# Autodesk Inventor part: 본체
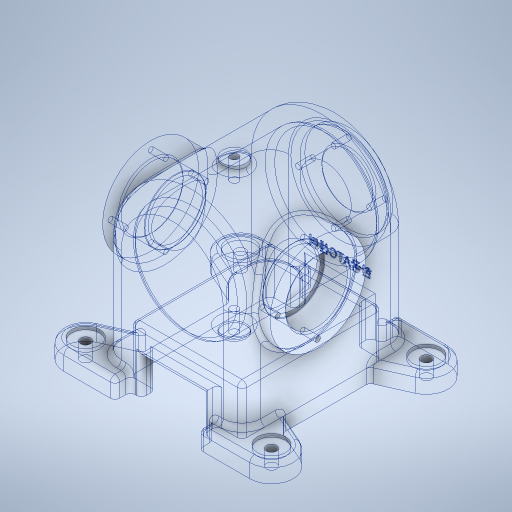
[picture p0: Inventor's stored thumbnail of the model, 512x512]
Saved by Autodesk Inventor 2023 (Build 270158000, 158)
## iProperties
Created: 2024-09
Part Number: 본체
Material: 알루미늄 6061
Document SubType Name: Modeling
Designer: home
Density: 2.7 g/cm^3
Appearance: 알루미늄 - 평지
Mass: 1473.92 g
Surface Area: 1119.68 cm^2
Volume: 545.898 cm^3
Author: home
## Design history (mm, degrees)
sketch "스케치1" dims "d2" = 90
  geometry: L1 (-45, 76)-(45, 76); L2 (45, 76)-(45, 0); L3 (45, 0)-(-45, 0); L4 (-45, 0)-(-45, 76); 6 further points
  constraints: 8 end point, 2 midpoint, 2 parallel, 1 coincident, 1 horizontal, 1 perpendicular, 3 other
  dimensions: "d0" = 90 distance of L2.end L3.end; "d7" = 121 distance from line of L3 point (0, 121); "d8" = 76 distance of L3.end L1.start
extrude "돌출1" new body sketch "스케치1" stored distance "d3" = 108; taper "d4" = 0 deg
sketch "스케치2"
  geometry: L1 (-45, 0)-(45, 0) reference; C1 r 28.5 at (0, 76); 1 further point
  constraints: 1 centre point
  dimensions: "d5" = 57 diameter of C1; "d6" = 76 distance from line of L1 C1.centre
extrude "돌출2" join sketch "스케치2" distance "d9" = 6; taper "d10" = 0 deg
node "작업 평면1"
sketch "스케치4"
  geometry: C1 r 16.5 at (0, 0); 1 further point
  constraints: 1 centre point, 1 vertical alignment
  dimensions: "d16" = 33 diameter of C1
extrude "돌출3" cut sketch "스케치4" distance "d17" = 15; taper "d18" = 0 deg
sketch "스케치6"
  geometry: L1 (27, 64)-(60, 64); L2 (65.693, 37.21)-(45, 28); L3 (45, 54)-(-45, 54) reference; L4 (45, 54)-(45, -54) reference; L5 (27, 64)-(27, 54); L6 (0, 54)-(0, 0); L7 (45, -54)-(45, 54) reference; A1 r 14 centre (60, 50) between (60, 64) and (65.693, 37.21); 3 further points
  constraints: 8 end point, 2 point on circle, 2 tangent, 2 vertical, 1 centre point, 1 coincident, 1 horizontal alignment, 1 midpoint, 1 vertical alignment
  dimensions: "d23" = 36 distance from line of L1 point (45, 28); "d25" = 18 distance from line of L4 L1.start; "d26" = 60 distance from line of L6 A1.centre; "d27" = 50 vertical distance of A1.centre L6.end; "d28" = 14 distance from line of L1 A1.centre
extrude "돌출5" join sketch "스케치6" distance "d29" = 12; taper "d30" = 0 deg
sketch "스케치7"
  geometry: L1 (-60, -64)-(-27, -64) reference; L2 (0, 66.899)-(0, -57.494); 2 further points
  constraints: 2 end point, 1 vertical
  dimensions: "d32" = 14 distance from line of L1 point (-60, -50); "d33" = 60 horizontal distance of point (-60, -50) L2.end
hole "구멍1" sketch "스케치7" at (-60, -50) diameter "d34" = 6.6; stored, may be unused: countersink angle "d38" = 90 deg, drill point angle "d40" = 0 deg; dims "d35" = 6, "d36" = 18, "d37" = 2, "d39" = 12
sketch "스케치8"
  geometry: L1 (-20, 23)-(20, 23); L2 (20, 23)-(20, 0); L3 (20, 0)-(-20, 0); L4 (-20, 0)-(-20, 23); L5 (-27, 0)-(27, 0) reference; 2 further points
  constraints: 8 end point, 2 midpoint, 2 parallel, 1 horizontal, 1 perpendicular
  dimensions: "d41" = 40 distance of L2.end L3.end; "d42" = 23 distance of L3.end L1.start
extrude "돌출6" cut sketch "스케치8" extent not by distance; stored distance "d43" = 0; taper "d44" = 0 deg
sketch "스케치9"
  geometry: L1 (-63, -19)-(9, -19); L2 (9, -19)-(9, -109); L3 (9, -109)-(-63, -109); L4 (-63, -109)-(-63, -19); L5 (-63, -19)-(9, -109); L6 (9, -19)-(-63, -109); L7 (18, -92)-(18, -36) reference; L8 (-55.5, -124)-(1.5, -124) reference; L9 (0, -118)-(-7, -118) reference; 1 further point
  constraints: 12 end point, 2 midpoint, 2 parallel, 1 horizontal, 1 perpendicular
  dimensions: "d45" = 9 distance between parallel lines of L7 L2; "d47" = 9 distance between parallel lines of L9 L3
extrude "돌출7" cut sketch "스케치9" distance "d48" = 31; taper "d49" = 0 deg
node "작업 평면2"
sketch "스케치10"
  geometry: L1 (-28.5, -60)-(28.5, -60) reference; C1 r 7.5 at (0, 14); 1 further point
  constraints: 1 centre point, 1 vertical alignment
  dimensions: "d51" = 74 distance from line of L1 C1.centre; "d52" = 15 diameter of C1
extrude "돌출8" join sketch "스케치10" distance "d53" = 7; taper "d54" = 0 deg
node "작업 평면3"
sketch "스케치11"
  geometry: 2 further points
hole "구멍2" sketch "스케치11" at (0, 0) diameter "d56" = 5.1881; stored, may be unused: countersink angle "d60" = 90 deg, drill point angle "d62" = 0 deg; dims "d57" = 12, "d58" = 18, "d59" = 2, "d61" = 8
fillet "모깎기2" dims "d63" = 3
sketch "스케치12" dims "d64" = 46
  geometry: 3 further points
  constraints: 1 vertical alignment, 2 other
hole "구멍3" sketch "스케치12" at (0, 23) diameter "d65" = 3.242; stored, may be unused: countersink angle "d69" = 90 deg, drill point angle "d71" = 0 deg; dims "d66" = 8, "d67" = 4, "d68" = 2, "d70" = 10
fillet "모깎기3" dims "d75" = 12
fillet "모깎기4" dims "d76" = 3
fillet "모깎기5" dims "d77" = 3
fillet "모깎기6" dims "d78" = 3
fillet "모깎기7" dims "d79" = 3
node "작업 평면4"
sketch "스케치13"
  geometry: L1 (54, -31)-(-54, -31); L2 (-54, -31)-(-54, 31); L3 (-54, 31)-(54, 31); L4 (54, 31)-(54, -31); L5 (54, -31)-(-54, 31); L6 (-54, -31)-(54, 31); L7 (-54, 0)-(54, 0); L8 (-60, -76)-(-74, -76) reference; 4 further points
  constraints: 14 end point, 5 midpoint, 2 parallel, 1 horizontal, 1 perpendicular, 1 vertical alignment
  dimensions: "d81" = 62 diameter of L3 L7; "d82" = 76 distance between parallel lines of L8 L7; "d83" = 108 distance of L2.end L3.end
revolve "회전2" sketch "스케치13" stored, may be unused: angle "d84" = 90 deg
sketch "스케치14"
  geometry: C1 r 20 at (0, 0); 1 further point
  constraints: 1 centre point
  dimensions: "d85" = 40 diameter of C1
extrude "돌출9" cut sketch "스케치14" distance "d86" = 16; taper "d87" = 0 deg
sketch "스케치15"
  geometry: C1 r 17.5 at (0, 0); 1 further point
  constraints: 1 centre point
  dimensions: "d88" = 35 diameter of C1
extrude "돌출10" cut sketch "스케치15" extent not by distance; stored distance "d89" = 0; taper "d90" = 0 deg
sketch "스케치16"
  geometry: C1 r 20 at (0, 0); 1 further point
  constraints: 1 centre point
  dimensions: "d91" = 40 diameter of C1
extrude "돌출11" cut sketch "스케치16" distance "d92" = 16; taper "d93" = 0 deg
fillet "모깎기8" dims "d94" = 0.3
sketch "스케치17" dims "d95" = 52
  geometry: 3 further points
  constraints: 1 vertical alignment, 2 other
hole "구멍4" sketch "스케치17" at (0, 26) diameter "d96" = 3.242; stored, may be unused: countersink angle "d100" = 90 deg, drill point angle "d102" = 0 deg; dims "d97" = 8, "d98" = 4, "d99" = 2, "d101" = 10
fillet "모깎기9" dims "d106" = 3
chamfer "모따기1" distance "d107" = 1; stored, may be unused: second distance "d108" = 2, angle "d109" = 45 deg
chamfer "모따기2" distance "d110" = 1; stored, may be unused: second distance "d111" = 2, angle "d112" = 45 deg
chamfer "모따기3" distance "d113" = 1; stored, may be unused: second distance "d114" = 2, angle "d115" = 45 deg
sketch "스케치18"
  geometry: L1 (-60, 0)-(-30, 0) reference; 2 further points
  constraints: 1 vertical alignment, 1 other
  dimensions: "d116" = 35 distance from line of L1 point (0, 35)
feature "엠보싱1" sketch "스케치18" dims "d117" = 0.5, "d118" = 0
sketch "스케치19"
  geometry: C1 r 36 at (0, 0); 1 further point
  constraints: 1 centre point
  dimensions: "d119" = 72 diameter of C1
extrude "돌출12" cut sketch "스케치19" distance "d120" = 90; taper "d121" = 0 deg
fillet "모깎기10" dims "d122" = 3
feature "̖耀̘耀̚耀̜耀̞耀̠耀̢耀̤耀" dims "d0" = 90, "d2" = 90, "d3" = 108, "d4" = 0, "d5" = 57, "d6" = 76, "d7" = 121, "d8" = 76, "d9" = 6, "d10" = 0, "d11" = -74, "d16" = 33, "d17" = 15, "d18" = 0, "d23" = 36, "d25" = 18, "d26" = 60, "d27" = 50, "d28" = 14, "d29" = 12, "d30" = 0, "d32" = 14, "d33" = 60, "d34" = 6.6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
feature "ԧ耀ԩ耀ԫ耀ԭ耀ԯ耀Ա耀Գ耀Ե耀" dims "d0" = 90, "d2" = 90, "d3" = 108, "d4" = 0, "d5" = 57, "d6" = 76, "d7" = 121, "d8" = 76, "d9" = 6, "d10" = 0, "d11" = -74, "d16" = 33, "d17" = 15, "d18" = 0, "d23" = 36, "d25" = 18, "d26" = 60, "d27" = 50, "d28" = 14, "d29" = 12, "d30" = 0, "d32" = 14, "d33" = 60, "d34" = 6.6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
node "솔리드1"
mirror "미러1"
mirror "미러2"
mirror "미러3"
pattern_circular "원형 패턴1" dims angle "d73" = 360 deg
pattern_circular "원형 패턴2" dims angle "d104" = 360 deg
mirror "미러4"
feature "A9D066F2-1C7D-4E18-AEED-F7BC21143FA4" dims "d34" = 6.6, "d35" = 6, "d36" = 18, "d37" = 2, "d38" = 90 deg, "d39" = 12, "d40" = 0
